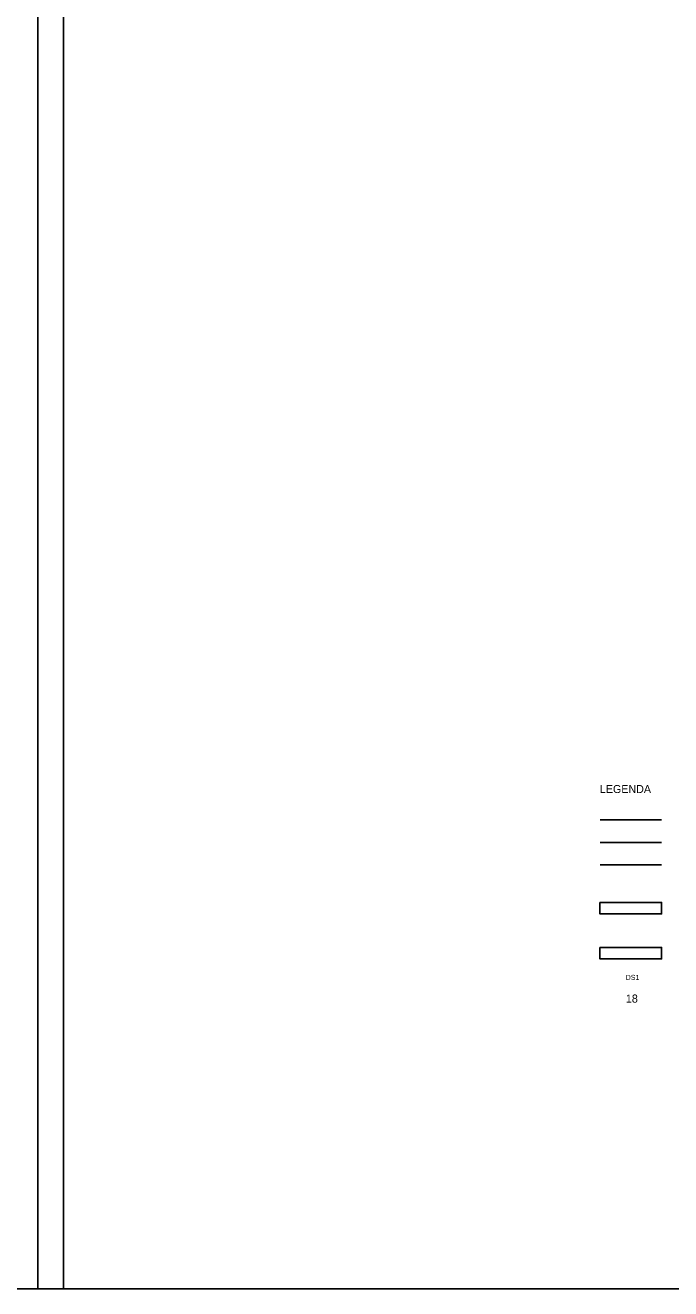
# Model space of a CAD drawing. Extents: x -477596 to -464945, y -1159281 to -1149080.
# Drawn here: x -468170 to -466899, y -1159280 to -1156794 of the extents above; entities that cross this region are included whole.
import ezdxf

# ---------------------------------------------------------------- set-up
doc = ezdxf.new("R2010")
doc.units = 0
for name, color, linetype in [('KLAD_LISTŮ', 7, 'Continuous'), ('NZ nezastavěná smíšená', 7, 'Continuous'), ('popis vps', 7, 'Continuous'), ('rámeček_pdf', 7, 'Continuous'), ('smíšená_nezastavitelná', 7, 'Continuous'), ('vodni_tok_prir', 7, 'Continuous'), ('zemědělské_plochy', 7, 'Continuous')]:
    doc.layers.add(name, color=color, linetype=linetype)

msp = doc.modelspace()

# ---------------------------------------------------------------- linework, layer by layer
at = {"layer": 'KLAD_LISTŮ'}
for points in [[(-471294.8, -1159279.9), (-468094.8, -1159279.9), (-468094.8, -1154154.9), (-471294.8, -1154154.9)], [(-468144.8, -1159279.9), (-464944.8, -1159279.9), (-464944.8, -1154154.9), (-468144.8, -1154154.9)]]:
    msp.add_lwpolyline(points, close=True, dxfattribs=at)
at = {"layer": 'rámeček_pdf'}
msp.add_lwpolyline([(-477596, -1149079.9), (-465194.8, -1149079.9), (-465194.8, -1159279.9), (-477596, -1159279.9)], close=True, dxfattribs=at)
at = {"layer": 'vodni_tok_prir'}
for points in [[(-467038.3, -1158519.8), (-466916.8, -1158519.8), (-466916.8, -1158542.3), (-467038.3, -1158542.3)], [(-467038.3, -1158608.3), (-466916.8, -1158608.3), (-466916.8, -1158630.8), (-467038.3, -1158630.8)]]:
    msp.add_lwpolyline(points, close=True, dxfattribs=at)
at = {"layer": 'zemědělské_plochy'}
for p, q in [((-467037.8, -1158357.4), (-466917.1, -1158357.4)), ((-467037.8, -1158401.6), (-466917.1, -1158401.6)), ((-467037.8, -1158445.9), (-466917.1, -1158445.9))]:
    msp.add_line(p, q, dxfattribs=at)

# ---------------------------------------------------------------- texts
at = {"layer": 'NZ nezastavěná smíšená'}
msp.add_text('LEGENDA', height=15.75, dxfattribs=at).set_placement((-467038.3, -1158304.6))
at = {"layer": 'popis vps'}
msp.add_text('DS1', height=10, dxfattribs=at).set_placement((-466987.4, -1158672.3))
at = {"layer": 'smíšená_nezastavitelná'}
msp.add_text('18', height=16, dxfattribs=at).set_placement((-466987.3, -1158717))

doc.saveas('drawing.dxf')
